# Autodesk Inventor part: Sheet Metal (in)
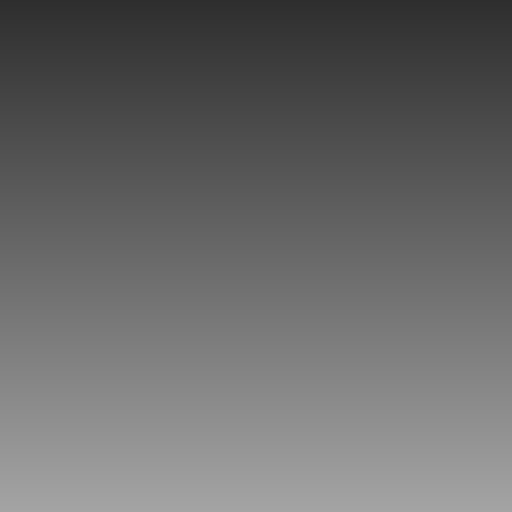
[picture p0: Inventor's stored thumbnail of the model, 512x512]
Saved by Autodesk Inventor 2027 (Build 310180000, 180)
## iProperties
Shininess: 64.0
Length Units: 11272
Angle Units: 11279
Time Units: 11290
Mass Units: 11286
Length Display Precision: 3
Angle Display Precision: 2
Compacted: True
Part Number: Sheet Metal (in)
Document SubType Name: Sheet Metal
Created: 2002-07
Material: Generic
Density: 1 g/cm^3
Sheet Metal Rule: Default
Appearance: Default
Density: 0.0
Volumn: 0.0
Area: 0.0
PropertySet Name: Model Information
Control State: 0
Master: False
Checked Out: False
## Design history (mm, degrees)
other parameters: "Thickness" = 3.048, "BendRadius" = 3.048 (= Thickness), "BendReliefWidth" = 3.048 (= Thickness), "BendReliefDepth" = 1.524 (= 0.5 x Thickness), "CornerReliefSize" = 12.192 (= 4 x Thickness), "SeamGap" = 0.00508, "MinimumRemnant" = 6.096 (= 2 x Thickness), "TransitionRadius" = 3.048 (= BendRadius), "JacobiRadiusSize" = 3.048 (= BendRadius), "GapSize" = 3.048 (= Thickness)
